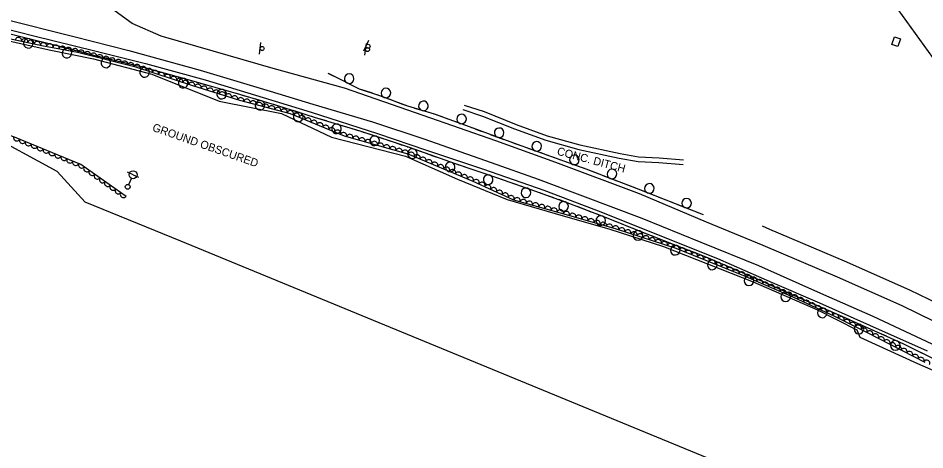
# Model space of a CAD drawing. Extents: x 1746719 to 1766531, y 631721 to 662391.
# Drawn here: x 1754959 to 1755525, y 646826 to 647096 of the extents above; entities that cross this region are included whole.
import ezdxf

# ---------------------------------------------------------------- set-up
doc = ezdxf.new("R2010")
doc.units = 0
for name, color, linetype in [('SURVEY - AERIAL SURVEY - Photo Control - Points - Elevations', 7, 'Continuous'), ('SURVEY - AERIAL SURVEY - Photo Control - Points - Locators', 7, 'Continuous'), ('SURVEY - AERIAL SURVEY - Photo Control - Points - Numbers', 7, 'Continuous'), ('SURVEY - AERIAL SURVEY - Photo Control with Text', 7, 'Continuous'), ('SURVEY - CENTERLINE - Existing Roads - Development', 7, 'Continuous'), ('SURVEY - CENTERLINE - Existing Roads Text', 7, 'Continuous'), ('SURVEY - CENTERLINE - Preliminary - Development', 7, 'Continuous'), ('SURVEY - CENTERLINE - Preliminary Curve Text', 7, 'Continuous'), ('SURVEY - CONTROL - Grid', 7, 'Continuous')]:
    doc.layers.add(name, color=color, linetype=linetype)

msp = doc.modelspace()

# ---------------------------------------------------------------- linework, layer by layer
at = {"layer": 'SURVEY - AERIAL SURVEY - Photo Control - Points - Elevations'}
msp.add_line((1755543.32, 647052.94), (1755496.66, 647118.04), dxfattribs=at)
for points in [[(1755541.47, 646901.15), (1755511.25, 646915.81), (1755470.9, 646933.77), (1755424.34, 646953.57), (1755389.09, 646968.25), (1755347.2, 646985.85), (1755294.89, 647005.47), (1755257.47, 647019.04), (1755212.01, 647034.88), (1755162.98, 647051.98), (1755118.31, 647064.2), (1755080.84, 647075.03), (1755048.51, 647084.46), (1755030.44, 647092.34), (1755019.67, 647100.14), (1755010.8, 647109.79), (1755006.52, 647118.04), (1754998.66, 647138.81), (1754985.94, 647173.6), (1754973.04, 647206.18), (1754963.8, 647228.69)], [(1754929.53, 647094.68), (1754968.95, 647084.72), (1755007.12, 647075.21), (1755038.66, 647067.4), (1755075.86, 647057.07), (1755112.24, 647046.03), (1755142.17, 647036.95), (1755183.53, 647023.7), (1755214.17, 647013.27), (1755249.78, 647001.31), (1755287.41, 646988.11), (1755323.1, 646974.59), (1755354.61, 646961.97), (1755395.98, 646945.48), (1755430.04, 646930.6), (1755459.55, 646917.77), (1755490.85, 646903.78), (1755526.86, 646887.77)], [(1754949.05, 647095.46), (1754993.86, 647084.27), (1755028.2, 647075.52), (1755072.84, 647063.13), (1755116.55, 647050.17), (1755143.24, 647041.89), (1755180.48, 647030.82), (1755212.51, 647020.26), (1755254.53, 647005.6), (1755283.9, 646994.99), (1755311.59, 646984.69), (1755348.61, 646970.69), (1755385.47, 646955.8), (1755421.54, 646941.15), (1755460.11, 646923.89), (1755492.92, 646909.39), (1755539.92, 646887.28)], [(1755686.46, 646835.36), (1755664.1, 646849.72), (1755643.33, 646861.7), (1755618.73, 646875.3), (1755591.95, 646889.28), (1755546.24, 646911.07), (1755515.89, 646925.79), (1755475.28, 646943.86), (1755428.6, 646963.71), (1755423.95, 646965.64)]]:
    msp.add_lwpolyline(points, dxfattribs=at)
at = {"layer": 'SURVEY - AERIAL SURVEY - Photo Control - Points - Locators'}
for points in [[(1755540.48, 646773.89), (1755523.36, 646791.15), (1755503.07, 646773.96), (1755060.76, 646956.34), (1755000.9, 646980.66), (1754983.46, 646999.86), (1754938.16, 647024.45), (1754891.57, 647037.43), (1754849.89, 647051.93), (1754799.99, 647060.64), (1754755.05, 647068.19), (1754713.05, 647072.69), (1754707.83, 647073.1), (1754667.43, 647072.04), (1754596.51, 647066.3), (1754581.75, 647053.3), (1754535.3, 647048.55), (1754481.05, 647047.31), (1754458.56, 647040.27), (1754452.78, 647025.88), (1754321.83, 647031.68), (1754312.68, 647033.88), (1754312.87, 647057.08), (1754316.71, 647138.76)], [(1754932.58, 647086.15), (1754978.58, 647075.92), (1755006.24, 647070.38), (1755042.67, 647060.61), (1755084.67, 647043.86), (1755123.61, 647036.04), (1755154.84, 647021.38), (1755201.09, 647009.55), (1755233.51, 646995.17), (1755264.62, 646982.36), (1755299.42, 646972.15), (1755328.06, 646964.05), (1755362.22, 646953.1), (1755418.2, 646930.83), (1755458.37, 646913.36), (1755482.84, 646901), (1755484.69, 646896.4), (1755520.76, 646879.97), (1755549.53, 646867.41)]]:
    msp.add_lwpolyline(points, dxfattribs=at)
at = {"layer": 'SURVEY - AERIAL SURVEY - Photo Control - Points - Numbers'}
for points in [[(1754940.68, 647089.24), (1754964.24, 647083.36), (1754981.86, 647078.95), (1755005.61, 647072.81), (1755037.27, 647065.16), (1755067.49, 647056.68), (1755097.9, 647048.02), (1755121.1, 647041.11), (1755144.01, 647033.93), (1755172.59, 647025.25), (1755203.26, 647014.99), (1755231.99, 647004.86), (1755257.78, 646996.19), (1755281.67, 646987.82), (1755303.53, 646979.93), (1755326.37, 646971.07), (1755345.83, 646963.3), (1755368.24, 646954.39), (1755386.6, 646947.32), (1755404.99, 646939.43), (1755423.67, 646931.35), (1755443.84, 646922.44), (1755465.5, 646912.93), (1755489.34, 646902.38), (1755512.02, 646892.19), (1755532.64, 646882.05)], [(1754961.74, 647083.99), (1754964.24, 647083.36), (1754970.67, 647081.76)], [(1754973.77, 647080.98), (1754978.33, 647079.84)], [(1754978.33, 647079.84), (1754981.86, 647078.95), (1754982.89, 647078.69)], [(1754985.99, 647077.89), (1754994.89, 647075.58)], [(1754997.99, 647074.78), (1755002.54, 647073.61)], [(1755002.54, 647073.61), (1755005.61, 647072.81), (1755007.1, 647072.45)], [(1755010.21, 647071.7), (1755019.15, 647069.54)], [(1755022.26, 647068.79), (1755026.83, 647067.68)], [(1755026.83, 647067.68), (1755031.4, 647066.58)], [(1755034.51, 647065.83), (1755037.27, 647065.16), (1755043.39, 647063.44)], [(1755046.47, 647062.58), (1755051, 647061.31)], [(1755051, 647061.31), (1755055.52, 647060.03)], [(1755058.6, 647059.17), (1755067.46, 647056.68)], [(1755387.06, 646972.72), (1755345.29, 646989.25), (1755313.94, 647001.28), (1755283.76, 647012.18), (1755266.33, 647018.34), (1755243.25, 647026.88), (1755219.17, 647035.64), (1755202.53, 647040.65), (1755184.99, 647047.2), (1755172.37, 647051.41), (1755160.37, 647057.29), (1755152.8, 647061.12)], [(1755153.3, 647060.87), (1755152.8, 647061.12)], [(1755157.49, 647058.75), (1755153.3, 647060.87)], [(1755168.61, 647053.26), (1755160.37, 647057.29), (1755160.35, 647057.31)], [(1755070.54, 647055.81), (1755075.06, 647054.52)], [(1755075.06, 647054.52), (1755079.58, 647053.23)], [(1755082.66, 647052.36), (1755091.51, 647049.84)], [(1755175.89, 647050.23), (1755172.37, 647051.41), (1755171.48, 647051.85)], [(1755094.58, 647048.96), (1755097.9, 647048.02), (1755099.1, 647047.66)], [(1755099.1, 647047.66), (1755103.6, 647046.32)], [(1755106.67, 647045.41), (1755115.49, 647042.78)], [(1755180.35, 647048.75), (1755175.89, 647050.23)], [(1755192.02, 647044.57), (1755184.99, 647047.2), (1755183.38, 647047.73)], [(1755118.55, 647041.87), (1755121.1, 647041.11), (1755123.05, 647040.5)], [(1755123.05, 647040.5), (1755127.54, 647039.09)], [(1755199.42, 647041.81), (1755195.02, 647043.45)], [(1755203.85, 647040.25), (1755202.53, 647040.65), (1755199.42, 647041.81)], [(1755130.59, 647038.14), (1755139.37, 647035.39)], [(1755142.42, 647034.43), (1755144.01, 647033.93), (1755146.92, 647033.05)], [(1755215.73, 647036.68), (1755206.92, 647039.33)], [(1755223.22, 647034.17), (1755219.17, 647035.64), (1755218.79, 647035.76)], [(1755227.63, 647032.56), (1755223.22, 647034.17)], [(1755146.92, 647033.05), (1755151.41, 647031.68)], [(1755154.47, 647030.75), (1755163.28, 647028.08)], [(1755239.28, 647028.32), (1755230.64, 647031.47)], [(1755166.34, 647027.15), (1755170.83, 647025.78)], [(1755170.83, 647025.78), (1755172.59, 647025.25), (1755175.31, 647024.34)], [(1755178.34, 647023.32), (1755187.07, 647020.4)], [(1755246.7, 647025.6), (1755243.25, 647026.88), (1755242.29, 647027.23)], [(1755251.11, 647023.97), (1755246.7, 647025.6)], [(1755262.74, 647019.67), (1755254.11, 647022.86)], [(1755190.1, 647019.39), (1755194.56, 647017.9)], [(1755194.56, 647017.9), (1755199.02, 647016.41)], [(1755270.17, 647016.99), (1755266.33, 647018.34), (1755265.74, 647018.56)], [(1755274.6, 647015.42), (1755270.17, 647016.99)], [(1755202.05, 647015.39), (1755203.26, 647014.99), (1755210.73, 647012.35)], [(1755213.75, 647011.29), (1755218.18, 647009.72)], [(1755286.29, 647011.27), (1755283.76, 647012.18), (1755277.62, 647014.35)], [(1755218.18, 647009.72), (1755222.62, 647008.16)], [(1755225.64, 647007.1), (1755231.99, 647004.86), (1755234.32, 647004.07)], [(1755293.72, 647008.59), (1755289.3, 647010.18)], [(1755298.14, 647006.99), (1755293.72, 647008.59)], [(1755309.8, 647002.78), (1755301.15, 647005.9)], [(1755237.36, 647003.05), (1755241.81, 647001.56)], [(1755241.81, 647001.56), (1755246.27, 647000.06)], [(1755317.21, 647000.03), (1755313.94, 647001.28), (1755312.81, 647001.69)], [(1755321.59, 646998.34), (1755317.21, 647000.03)], [(1755249.3, 646999.04), (1755257.78, 646996.19), (1755258.02, 646996.1)], [(1755261.04, 646995.05), (1755265.48, 646993.49)], [(1755333.17, 646993.9), (1755324.58, 646997.2)], [(1755265.48, 646993.49), (1755269.91, 646991.94)], [(1755272.93, 646990.88), (1755281.61, 646987.84)], [(1755340.54, 646991.07), (1755336.16, 646992.75)], [(1755344.93, 646989.39), (1755340.54, 646991.07)], [(1755284.62, 646986.76), (1755289.04, 646985.16)], [(1755289.04, 646985.16), (1755293.47, 646983.56)], [(1755356.46, 646984.83), (1755347.91, 646988.21)], [(1755363.81, 646981.92), (1755359.44, 646983.65)], [(1755296.48, 646982.48), (1755303.53, 646979.93), (1755305.11, 646979.31)], [(1755308.1, 646978.16), (1755312.48, 646976.46)], [(1755368.18, 646980.19), (1755363.81, 646981.92)], [(1755379.71, 646975.63), (1755371.16, 646979.01)], [(1755312.48, 646976.46), (1755316.86, 646974.76)], [(1755319.85, 646973.6), (1755326.37, 646971.07), (1755328.42, 646970.26)], [(1755387.06, 646972.72), (1755382.69, 646974.45)], [(1755331.39, 646969.07), (1755335.75, 646967.33)], [(1755335.75, 646967.33), (1755340.12, 646965.58)], [(1755343.09, 646964.4), (1755345.83, 646963.3), (1755351.64, 646960.99)], [(1755354.61, 646959.81), (1755358.98, 646958.07)], [(1755358.98, 646958.07), (1755363.34, 646956.34)], [(1755366.32, 646955.15), (1755368.24, 646954.39), (1755374.9, 646951.83)], [(1755377.88, 646950.68), (1755382.27, 646948.99)], [(1755382.27, 646948.99), (1755386.6, 646947.32), (1755386.65, 646947.3)], [(1755389.59, 646946.04), (1755398.05, 646942.41)], [(1755400.99, 646941.15), (1755404.99, 646939.43), (1755405.31, 646939.29)], [(1755405.31, 646939.29), (1755409.62, 646937.43)], [(1755412.56, 646936.16), (1755421, 646932.5)], [(1755423.94, 646931.23), (1755428.24, 646929.33)], [(1755428.24, 646929.33), (1755432.54, 646927.43)], [(1755435.46, 646926.14), (1755443.84, 646922.44), (1755443.88, 646922.42)], [(1755446.81, 646921.14), (1755451.11, 646919.25)], [(1755451.11, 646919.25), (1755455.42, 646917.36)], [(1755458.35, 646916.07), (1755465.5, 646912.93), (1755466.77, 646912.37)], [(1755469.7, 646911.08), (1755473.99, 646909.17)], [(1755473.99, 646909.17), (1755478.29, 646907.27)], [(1755481.22, 646905.98), (1755489.34, 646902.38), (1755489.63, 646902.25)], [(1755492.55, 646900.94), (1755496.84, 646899.01)], [(1755496.84, 646899.01), (1755501.12, 646897.08)], [(1755504.04, 646895.77), (1755512.02, 646892.19), (1755512.43, 646891.98)], [(1755515.3, 646890.57), (1755519.52, 646888.5)], [(1755519.52, 646888.5), (1755523.73, 646886.43)]]:
    msp.add_lwpolyline(points, dxfattribs=at)
for centre, start, end in [((1754965.43, 647079.98), 189.2154, 189.2014), ((1754989.64, 647073.84), 188.77, 188.756), ((1755013.93, 647067.72), 189.6756, 189.6616), ((1755038.11, 647061.81), 187.5856, 187.5716), ((1755062.18, 647055.05), 187.5856, 187.5716), ((1755165.84, 647057.95), 357.137, 357.123), ((1755086.22, 647048.22), 187.3776, 187.3636), ((1755188.8, 647048.97), 2.802, 2.788), ((1755110.18, 647041.23), 186.6854, 186.6714), ((1755212.23, 647040.86), 6.5241, 6.5101), ((1755134.04, 647033.91), 185.8779, 185.8639), ((1755236.03, 647032.7), 3.2703, 3.2563), ((1755157.96, 647026.56), 186.3664, 186.3524), ((1755259.51, 647024.06), 2.9744, 2.9604), ((1755181.71, 647019.03), 184.7697, 184.7557), ((1755283, 647015.63), 3.8054, 3.7914), ((1755205.36, 647011.07), 183.8455, 183.8315), ((1755228.93, 647002.75), 183.8455, 183.8315), ((1755306.53, 647007.15), 3.4079, 3.3939), ((1755329.99, 646998.33), 2.2679, 2.2539), ((1755252.66, 646994.74), 184.6877, 184.6737), ((1755276.24, 646986.55), 183.9715, 183.9575), ((1755353.33, 646989.29), 1.68, 1.666), ((1755376.58, 646980.09), 1.68, 1.666), ((1755299.74, 646978.11), 183.4134, 183.3994), ((1755323.01, 646969.16), 182.0736, 182.0596), ((1755346.21, 646959.92), 181.5796, 181.5656), ((1755369.48, 646950.7), 182.2253, 182.2114), ((1755392.6, 646941.49), 180.0395, 180.0255), ((1755415.55, 646931.59), 179.8655, 179.8515), ((1755438.42, 646921.55), 179.4366, 179.4226), ((1755461.31, 646911.49), 179.5743, 179.5604), ((1755484.17, 646901.39), 179.3999, 179.3859), ((1755506.97, 646891.17), 179.0549, 179.041)]:
    msp.add_arc(centre, 3, start, end, dxfattribs=at)
at = {"layer": 'SURVEY - AERIAL SURVEY - Photo Control with Text'}
for points in [[(1754933.79, 647087.14), (1754973.94, 647078.69), (1754996.27, 647074.5), (1755031.74, 647065.45), (1755067.97, 647053.61), (1755097.41, 647044.36), (1755129, 647036.12), (1755162.7, 647022.23), (1755202.42, 647010.93), (1755243.17, 646993.86), (1755268.51, 646982.26), (1755301.35, 646973.1), (1755332.5, 646963.94), (1755369.88, 646951.89), (1755412.13, 646934.77), (1755443.43, 646921.23), (1755468.86, 646909.38), (1755488.98, 646899.43), (1755525.38, 646880.6)], [(1755026.53, 646984.31), (1754998.25, 647004.23), (1754956.88, 647021.42), (1754914.76, 647036.55), (1754880.74, 647046.51), (1754848.9, 647052.65), (1754794.49, 647064.89), (1754753.65, 647070.4), (1754706.2, 647074.3), (1754656.89, 647071.37), (1754618.56, 647066.95), (1754594.15, 647065.07), (1754581.28, 647053.36), (1754536.3, 647048.62), (1754481.78, 647048.21), (1754456.93, 647040.01), (1754456.23, 647032.04)]]:
    msp.add_lwpolyline(points, dxfattribs=at)
for centre, major_axis in [((1754959.31, 647081.76), (1.96, -0.41)), ((1754963.23, 647080.94), (1.96, -0.41)), ((1754967.14, 647080.12), (1.96, -0.41)), ((1754971.06, 647079.29), (1.96, -0.41)), ((1754974.97, 647078.49), (1.97, -0.37)), ((1754978.91, 647077.75), (1.97, -0.37)), ((1754982.84, 647077.02), (1.97, -0.37)), ((1754986.77, 647076.28), (1.97, -0.37)), ((1754990.7, 647075.54), (1.97, -0.37)), ((1754994.63, 647074.81), (1.97, -0.37)), ((1754998.53, 647073.92), (1.94, -0.49)), ((1755002.41, 647072.93), (1.94, -0.49)), ((1755006.28, 647071.95), (1.94, -0.49)), ((1755010.16, 647070.96), (1.94, -0.49)), ((1755014.03, 647069.97), (1.94, -0.49)), ((1755017.91, 647068.98), (1.94, -0.49)), ((1755021.79, 647067.99), (1.94, -0.49)), ((1755025.66, 647067), (1.94, -0.49)), ((1755029.54, 647066.01), (1.94, -0.49)), ((1755033.38, 647064.92), (1.9, -0.62)), ((1755037.18, 647063.67), (1.9, -0.62)), ((1755040.99, 647062.43), (1.9, -0.62)), ((1755044.79, 647061.19), (1.9, -0.62)), ((1755048.59, 647059.95), (1.9, -0.62)), ((1755052.39, 647058.7), (1.9, -0.62)), ((1755056.2, 647057.46), (1.9, -0.62)), ((1755060, 647056.22), (1.9, -0.62)), ((1755063.8, 647054.97), (1.9, -0.62)), ((1755067.6, 647053.73), (1.9, -0.62)), ((1755071.42, 647052.53), (1.91, -0.6)), ((1755075.23, 647051.33), (1.91, -0.6)), ((1755079.05, 647050.13), (1.91, -0.6)), ((1755082.86, 647048.93), (1.91, -0.6)), ((1755086.68, 647047.73), (1.91, -0.6)), ((1755090.5, 647046.53), (1.91, -0.6)), ((1755094.31, 647045.33), (1.91, -0.6)), ((1755098.14, 647044.17), (1.94, -0.5)), ((1755102.01, 647043.16), (1.94, -0.5)), ((1755105.88, 647042.15), (1.94, -0.5)), ((1755109.75, 647041.14), (1.94, -0.5)), ((1755113.62, 647040.13), (1.94, -0.5)), ((1755117.49, 647039.12), (1.94, -0.5)), ((1755121.36, 647038.11), (1.94, -0.5)), ((1755125.23, 647037.1), (1.94, -0.5)), ((1755129.1, 647036.08), (1.85, -0.76)), ((1755132.8, 647034.56), (1.85, -0.76)), ((1755136.49, 647033.03), (1.85, -0.76)), ((1755140.19, 647031.51), (1.85, -0.76)), ((1755143.89, 647029.98), (1.85, -0.76)), ((1755147.59, 647028.46), (1.85, -0.76)), ((1755151.29, 647026.94), (1.85, -0.76)), ((1755154.99, 647025.41), (1.85, -0.76)), ((1755158.68, 647023.89), (1.85, -0.76)), ((1755162.38, 647022.36), (1.85, -0.76)), ((1755166.22, 647021.23), (1.92, -0.55)), ((1754958.16, 647020.88), (-1.85, 0.77)), ((1754961.86, 647019.35), (-1.85, 0.77)), ((1754965.55, 647017.81), (-1.85, 0.77)), ((1754969.25, 647016.28), (-1.85, 0.77)), ((1755170.06, 647020.14), (1.92, -0.55)), ((1755173.91, 647019.04), (1.92, -0.55)), ((1755177.76, 647017.95), (1.92, -0.55)), ((1755181.61, 647016.85), (1.92, -0.55)), ((1755185.45, 647015.76), (1.92, -0.55)), ((1755189.3, 647014.67), (1.92, -0.55)), ((1754972.94, 647014.75), (-1.85, 0.77)), ((1754976.63, 647013.21), (-1.85, 0.77)), ((1754980.33, 647011.68), (-1.85, 0.77)), ((1755193.15, 647013.57), (1.92, -0.55)), ((1755197, 647012.48), (1.92, -0.55)), ((1755200.84, 647011.38), (1.92, -0.55)), ((1755204.6, 647010.02), (1.84, -0.77)), ((1754984.02, 647010.14), (-1.85, 0.77)), ((1754987.72, 647008.61), (-1.85, 0.77)), ((1754991.41, 647007.07), (-1.85, 0.77)), ((1754995.1, 647005.54), (-1.85, 0.77)), ((1755208.29, 647008.48), (1.84, -0.77)), ((1755211.98, 647006.93), (1.84, -0.77)), ((1755215.67, 647005.39), (1.84, -0.77)), ((1755219.35, 647003.84), (1.84, -0.77)), ((1754998.73, 647003.89), (-1.63, 1.15)), ((1755002, 647001.58), (-1.63, 1.15)), ((1755005.27, 646999.28), (-1.63, 1.15)), ((1755223.04, 647002.29), (1.84, -0.77)), ((1755226.73, 647000.75), (1.84, -0.77)), ((1755230.42, 646999.2), (1.84, -0.77)), ((1755234.11, 646997.66), (1.84, -0.77)), ((1755008.54, 646996.98), (-1.63, 1.15)), ((1755011.81, 646994.67), (-1.63, 1.15)), ((1755237.8, 646996.11), (1.84, -0.77)), ((1755241.49, 646994.57), (1.84, -0.77)), ((1755245.15, 646992.96), (1.82, -0.83)), ((1755015.08, 646992.37), (-1.63, 1.15)), ((1755018.35, 646990.06), (-1.63, 1.15)), ((1755021.62, 646987.76), (-1.63, 1.15)), ((1755248.79, 646991.29), (1.82, -0.83)), ((1755252.42, 646989.62), (1.82, -0.83)), ((1755256.06, 646987.96), (1.82, -0.83)), ((1755259.7, 646986.29), (1.82, -0.83)), ((1755024.89, 646985.46), (-1.63, 1.15)), ((1755263.34, 646984.63), (1.82, -0.83)), ((1755266.97, 646982.96), (1.82, -0.83)), ((1755270.73, 646981.64), (1.93, -0.54)), ((1755274.59, 646980.56), (1.93, -0.54)), ((1755278.44, 646979.49), (1.93, -0.54)), ((1755282.29, 646978.42), (1.93, -0.54)), ((1755286.15, 646977.34), (1.93, -0.54)), ((1755290, 646976.27), (1.93, -0.54)), ((1755293.85, 646975.19), (1.93, -0.54)), ((1755297.71, 646974.12), (1.93, -0.54)), ((1755301.56, 646973.04), (1.92, -0.56)), ((1755305.39, 646971.91), (1.92, -0.56)), ((1755309.23, 646970.79), (1.92, -0.56)), ((1755313.07, 646969.66), (1.92, -0.56)), ((1755316.91, 646968.53), (1.92, -0.56)), ((1755320.74, 646967.4), (1.92, -0.56)), ((1755324.58, 646966.27), (1.92, -0.56)), ((1755328.42, 646965.14), (1.92, -0.56)), ((1755332.26, 646964.01), (1.92, -0.56)), ((1755336.07, 646962.79), (1.9, -0.61)), ((1755339.87, 646961.57), (1.9, -0.61)), ((1755343.68, 646960.34), (1.9, -0.61)), ((1755347.49, 646959.11), (1.9, -0.61)), ((1755351.29, 646957.88), (1.9, -0.61)), ((1755355.1, 646956.65), (1.9, -0.61)), ((1755358.91, 646955.43), (1.9, -0.61)), ((1755362.71, 646954.2), (1.9, -0.61)), ((1755366.52, 646952.97), (1.9, -0.61)), ((1755370.32, 646951.71), (1.85, -0.75)), ((1755374.02, 646950.21), (1.85, -0.75)), ((1755377.73, 646948.71), (1.85, -0.75)), ((1755381.44, 646947.21), (1.85, -0.75)), ((1755385.15, 646945.7), (1.85, -0.75)), ((1755388.85, 646944.2), (1.85, -0.75)), ((1755392.56, 646942.7), (1.85, -0.75)), ((1755396.27, 646941.2), (1.85, -0.75)), ((1755399.97, 646939.69), (1.85, -0.75)), ((1755403.68, 646938.19), (1.85, -0.75)), ((1755407.39, 646936.69), (1.85, -0.75)), ((1755411.1, 646935.19), (1.85, -0.75)), ((1755414.78, 646933.62), (1.84, -0.79)), ((1755418.45, 646932.04), (1.84, -0.79)), ((1755422.12, 646930.45), (1.84, -0.79)), ((1755425.79, 646928.86), (1.84, -0.79)), ((1755429.46, 646927.27), (1.84, -0.79)), ((1755433.14, 646925.69), (1.84, -0.79)), ((1755436.81, 646924.1), (1.84, -0.79)), ((1755440.48, 646922.51), (1.84, -0.79)), ((1755444.14, 646920.9), (1.81, -0.84)), ((1755447.77, 646919.21), (1.81, -0.84)), ((1755451.39, 646917.52), (1.81, -0.84)), ((1755455.02, 646915.83), (1.81, -0.84)), ((1755458.64, 646914.14), (1.81, -0.84)), ((1755462.27, 646912.46), (1.81, -0.84)), ((1755465.89, 646910.77), (1.81, -0.84)), ((1755469.51, 646909.06), (1.79, -0.89)), ((1755473.1, 646907.29), (1.79, -0.89)), ((1755476.68, 646905.51), (1.79, -0.89)), ((1755480.27, 646903.74), (1.79, -0.89)), ((1755483.85, 646901.97), (1.79, -0.89)), ((1755487.44, 646900.19), (1.79, -0.89)), ((1755491.01, 646898.38), (1.78, -0.92)), ((1755494.56, 646896.54), (1.78, -0.92)), ((1755498.11, 646894.71), (1.78, -0.92)), ((1755501.66, 646892.87), (1.78, -0.92)), ((1755505.22, 646891.03), (1.78, -0.92)), ((1755508.77, 646889.19), (1.78, -0.92)), ((1755512.32, 646887.36), (1.78, -0.92)), ((1755515.88, 646885.52), (1.78, -0.92)), ((1755519.43, 646883.68), (1.78, -0.92)), ((1755522.98, 646881.84), (1.78, -0.92)), ((1755526.55, 646880.04), (1.8, -0.87))]:
    msp.add_ellipse(centre, major_axis=major_axis, ratio=0.940188, start_param=0, end_param=3.141593, dxfattribs=at)
at = {"layer": 'SURVEY - CENTERLINE - Existing Roads - Development'}
for p, q in [((1755030.89, 646997.84), (1755027.46, 646999.36)), ((1755028.16, 646991.67), (1755029.88, 646995.56)), ((1755030.89, 646997.84), (1755034.32, 646996.33))]:
    msp.add_line(p, q, dxfattribs=at)
for centre, radius in [((1755030.89, 646997.84), 2.5), ((1755027.55, 646990.3), 1.5)]:
    msp.add_circle(centre, radius, dxfattribs=at)
at = {"layer": 'SURVEY - CENTERLINE - Existing Roads Text'}
for points in [[(1755237.68, 647041.43), (1755250.23, 647037.32), (1755270.1, 647029.29), (1755289.52, 647022.26), (1755309.91, 647016.51), (1755335.03, 647011.08), (1755346.63, 647009.02), (1755359.47, 647008.42), (1755374.6, 647007.17)], [(1755236.76, 647038.61), (1755249.21, 647034.53), (1755269.05, 647026.51), (1755288.63, 647019.42), (1755309.21, 647013.62), (1755334.46, 647008.16), (1755346.31, 647006.06), (1755359.29, 647005.45), (1755374.37, 647004.21)]]:
    msp.add_lwpolyline(points, dxfattribs=at)
at = {"layer": 'SURVEY - CENTERLINE - Preliminary Curve Text'}
msp.add_line((1755507.49, 647081.02), (1755507.49, 647081.02), dxfattribs=at)
msp.add_lwpolyline([(1755506.39, 647084.03), (1755510.18, 647082.75), (1755508.58, 647078.01), (1755504.79, 647079.29), (1755506.39, 647084.03)], dxfattribs=at)
at = {"layer": 'SURVEY - CONTROL - Grid'}
for p, q in [((1755109.82, 647073.15), (1755110.73, 647080.59)), ((1755175.02, 647075.21), (1755178.09, 647082.05)), ((1755175.57, 647072.55), (1755176.59, 647079.98))]:
    msp.add_line(p, q, dxfattribs=at)
for centre in [(1755177.68, 647078.14), (1755111.49, 647076.75), (1755177.3, 647076.12)]:
    msp.add_circle(centre, 1.25, dxfattribs=at)

# ---------------------------------------------------------------- texts
at = {"layer": 'SURVEY - AERIAL SURVEY - Photo Control - Points - Locators'}
msp.add_text('GROUND OBSCURED', height=5, rotation=340.7176, dxfattribs=at).set_placement((1755042.5, 647025.41))
at = {"layer": 'SURVEY - CENTERLINE - Preliminary - Development'}
msp.add_text('CONC. DITCH', height=5, rotation=344.9508, dxfattribs=at).set_placement((1755295.27, 647010.44))

doc.saveas('drawing.dxf')
